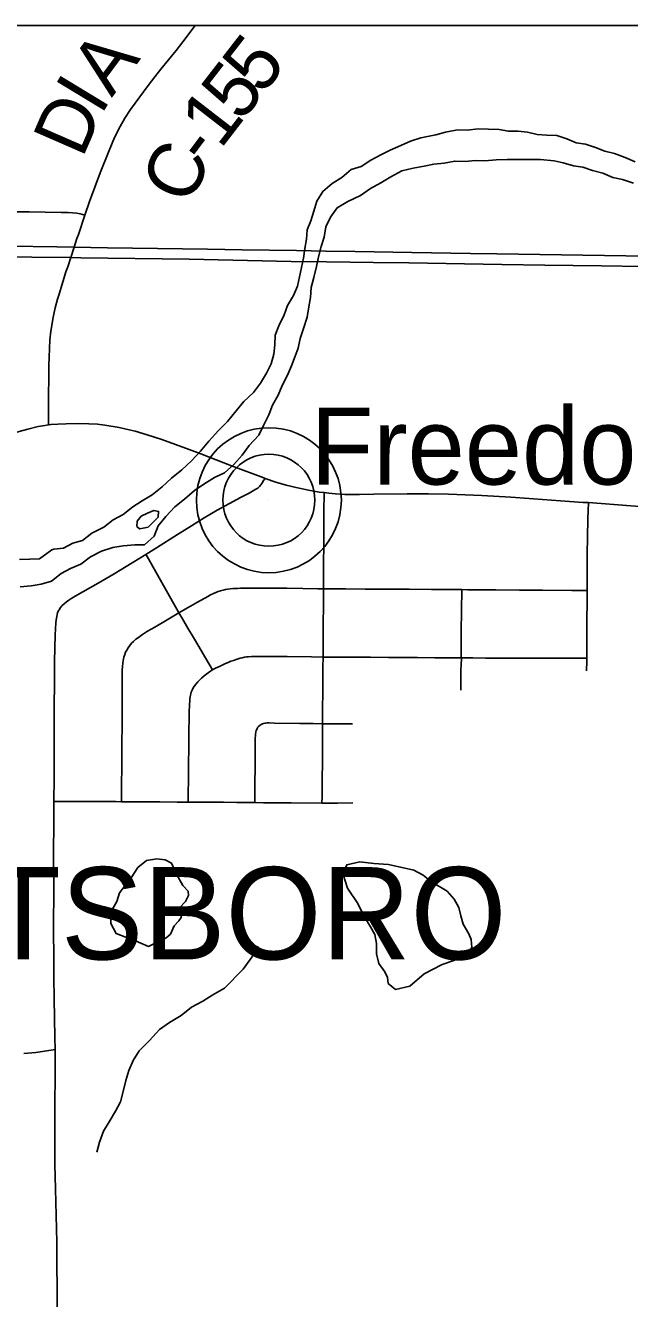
# Model space of a CAD drawing. Extents: x 0 to 34, y 0 to 22.
# Drawn here: x 5.511 to 6.131, y 19.311 to 20.617 of the extents above; entities that cross this region are included whole.
import ezdxf

# ---------------------------------------------------------------- set-up
doc = ezdxf.new("R2010")
doc.units = 0
for name, color, linetype in [('GM_X_Corporation', 7, 'Continuous'), ('GM_X_Corporation_Text', 7, 'Continuous'), ('GM_X_County_Road', 7, 'Continuous'), ('GM_X_County_Road_Text', 7, 'Continuous'), ('GM_X_Interstate_Route', 7, 'Continuous'), ('GM_X_Major_River', 7, 'Continuous'), ('GM_X_Minor_Lake', 7, 'Continuous'), ('GM_X_Minor_River', 7, 'Continuous'), ('GM_X_State_Route', 7, 'Continuous'), ('GM_X_Township_Road', 7, 'Continuous'), ('GM_X_Unincorporated', 7, 'Continuous'), ('GM_X_Unincorporated_Location', 7, 'Continuous'), ('GM_X_Unincorporated_Text', 7, 'Continuous'), ('SH_Data', 7, 'Continuous')]:
    doc.layers.add(name, color=color, linetype=linetype)

msp = doc.modelspace()

# ---------------------------------------------------------------- linework, layer by layer
at = {"layer": 'GM_X_Corporation'}
msp.add_lwpolyline([(8.914, 20.6173), (5.0338, 20.6173)], dxfattribs=at)
at = {"layer": 'GM_X_County_Road'}
for points in [[(5.5718, 20.4227), (5.5766, 20.4368), (5.5873, 20.466), (5.5966, 20.4891), (5.6022, 20.5023), (5.6078, 20.5135), (5.6127, 20.5222), (5.6185, 20.5311), (5.6366, 20.5556), (5.6435, 20.5645), (5.6497, 20.5723), (5.6653, 20.5916), (5.6722, 20.6004), (5.6849, 20.6173)], [(5.5387, 20.3154), (5.5388, 20.3164), (5.5413, 20.3274), (5.5437, 20.3364), (5.5449, 20.3406), (5.5462, 20.3448), (5.5472, 20.3483), (5.5523, 20.3644), (5.5541, 20.3696), (5.5572, 20.379), (5.5607, 20.3897), (5.5636, 20.3986), (5.565, 20.4027), (5.5718, 20.4227)], [(5.5342, 20.2074), (5.5342, 20.2173), (5.5344, 20.2289), (5.5342, 20.2356), (5.5346, 20.258), (5.5347, 20.2682), (5.5349, 20.2768), (5.5358, 20.2948), (5.5366, 20.3035), (5.5387, 20.3154)], [(5.423, 20.1689), (5.4421, 20.1772), (5.4639, 20.1863), (5.4773, 20.1914), (5.4931, 20.1971), (5.5041, 20.2006), (5.513, 20.203), (5.5236, 20.2056), (5.5307, 20.2069), (5.5342, 20.2074)], [(5.5398, 19.8211), (5.5401, 19.845), (5.5401, 19.8611), (5.5401, 19.879), (5.5401, 19.9029), (5.5401, 19.9222), (5.5404, 19.939), (5.5406, 19.9651), (5.5412, 19.9919), (5.5419, 20.0043), (5.5422, 20.0075), (5.5428, 20.0109), (5.5432, 20.0128), (5.5437, 20.0145), (5.5444, 20.0161), (5.5452, 20.0177), (5.5467, 20.0199)], [(5.5411, 19.5664), (5.5409, 19.5788), (5.5401, 19.6188), (5.5397, 19.6406), (5.5397, 19.6661), (5.5395, 19.6835), (5.5395, 19.6966), (5.5399, 19.7264), (5.5394, 19.766), (5.5397, 19.8015), (5.5398, 19.8211)], [(5.5434, 19.2978), (5.5429, 19.3687), (5.5417, 19.4234), (5.541, 19.4483), (5.5407, 19.4731), (5.5407, 19.4924), (5.5409, 19.5146), (5.5411, 19.5351), (5.5411, 19.5664)]]:
    msp.add_lwpolyline(points, dxfattribs=at)
at = {"layer": 'GM_X_Interstate_Route'}
for points in [[(5.0396, 20.398), (5.1655, 20.3959), (5.2516, 20.3944), (5.3154, 20.3934), (5.3505, 20.3929), (5.4941, 20.3908), (5.5428, 20.39), (5.5607, 20.3897), (5.5948, 20.3892), (5.6975, 20.3876), (5.733, 20.3871), (5.7889, 20.3862), (5.8192, 20.3858), (5.8492, 20.3853), (5.9073, 20.3843), (5.9674, 20.3834), (5.9946, 20.383), (6.061, 20.3819), (6.1271, 20.3809), (6.1811, 20.3797)], [(5.0386, 20.387), (5.1051, 20.386), (5.1744, 20.3851), (5.2381, 20.3842), (5.287, 20.3833), (5.3339, 20.3825), (5.3734, 20.3818), (5.4385, 20.3808), (5.4778, 20.3802), (5.5171, 20.3796), (5.5572, 20.379), (5.5674, 20.3789), (5.6788, 20.3774), (5.7835, 20.3752), (5.8199, 20.3748), (5.8681, 20.3742), (5.9044, 20.3738), (5.9999, 20.3721), (6.0438, 20.3714), (6.1022, 20.3705), (6.1443, 20.3698)]]:
    msp.add_lwpolyline(points, dxfattribs=at)
at = {"layer": 'GM_X_Major_River'}
msp.add_line((5.6368, 20.1023), (5.647, 20.1126), dxfattribs=at)
for points in [[(6.0759, 20.4967), (6.0664, 20.5008), (6.0561, 20.5042), (6.0459, 20.5048), (6.0361, 20.5055), (6.0262, 20.5077), (6.0164, 20.5088), (6.0065, 20.5087), (5.9971, 20.5105), (5.9861, 20.5108), (5.9755, 20.5111), (5.9641, 20.5099), (5.9543, 20.5102), (5.9418, 20.5078), (5.932, 20.5051), (5.9165, 20.5019), (5.9059, 20.4985), (5.8961, 20.4942), (5.8852, 20.4892), (5.8754, 20.4846), (5.8652, 20.4792), (5.8554, 20.4727), (5.8452, 20.4695), (5.8354, 20.4611), (5.8256, 20.455), (5.8159, 20.4469), (5.8099, 20.437), (5.8066, 20.4268), (5.8036, 20.4169), (5.7999, 20.4074), (5.7992, 20.3979), (5.7974, 20.3884), (5.796, 20.3785), (5.7941, 20.369), (5.7919, 20.3595), (5.7901, 20.3496), (5.786, 20.3401), (5.7797, 20.3298), (5.7763, 20.3203), (5.7708, 20.3089), (5.767, 20.2994), (5.7667, 20.2895), (5.7657, 20.28), (5.7631, 20.2702), (5.7583, 20.2606), (5.7519, 20.2503), (5.7448, 20.2408), (5.735, 20.2313), (5.7271, 20.2217), (5.7181, 20.211), (5.7088, 20.2015), (5.699, 20.1908), (5.6904, 20.1805), (5.681, 20.1705), (5.6712, 20.1613), (5.6607, 20.1529), (5.6509, 20.1437), (5.6408, 20.1357), (5.6306, 20.1296), (5.6208, 20.1234), (5.611, 20.1154), (5.6008, 20.11), (5.591, 20.1023), (5.579, 20.0962), (5.5692, 20.0889), (5.5594, 20.0861), (5.5496, 20.0808), (5.5397, 20.0799), (5.5379, 20.0792)], [(6.1366, 20.4775), (6.1263, 20.4819), (6.1153, 20.486), (6.1055, 20.4882), (6.096, 20.4919), (6.0857, 20.4953), (6.0759, 20.4967)], [(5.7875, 20.2779), (5.7907, 20.286), (5.7928, 20.2962), (5.7961, 20.3062), (5.7998, 20.318), (5.8016, 20.3286), (5.8033, 20.3381), (5.804, 20.3484), (5.8069, 20.3587), (5.8094, 20.3701), (5.8116, 20.38), (5.8141, 20.3903), (5.8174, 20.4002), (5.8192, 20.4105), (5.824, 20.4204), (5.8307, 20.43), (5.8416, 20.4366), (5.8548, 20.4428), (5.865, 20.4501), (5.8755, 20.4559), (5.8857, 20.4621), (5.897, 20.468), (5.9087, 20.4708), (5.92, 20.4728), (5.9298, 20.4748), (5.9404, 20.4761), (5.9514, 20.4781), (5.962, 20.4778), (5.9722, 20.4787), (5.9824, 20.4785), (5.9938, 20.4794), (6.0052, 20.4799), (6.0173, 20.4796), (6.0396, 20.4799), (6.0533, 20.4785), (6.0628, 20.4764), (6.0734, 20.4731), (6.0829, 20.472), (6.0928, 20.4684), (6.1034, 20.4658), (6.1137, 20.4614), (6.1236, 20.4592), (6.135, 20.4556)], [(5.5053, 20.0411), (5.5167, 20.0423), (5.5269, 20.044), (5.5375, 20.0471), (5.5472, 20.0548), (5.557, 20.0599), (5.5676, 20.0646), (5.5773, 20.0719), (5.5886, 20.0777), (5.6003, 20.0817), (5.6109, 20.0833), (5.623, 20.0842), (5.6329, 20.0843), (5.643, 20.0932), (5.647, 20.1039), (5.6549, 20.1135), (5.6642, 20.1234), (5.674, 20.1311), (5.6841, 20.14), (5.6939, 20.1466), (5.7048, 20.1535), (5.715, 20.1582), (5.7247, 20.1667), (5.733, 20.1763), (5.7404, 20.1862), (5.7502, 20.197), (5.755, 20.2069), (5.7605, 20.2176), (5.7642, 20.2275), (5.7702, 20.2378), (5.7742, 20.2478), (5.7798, 20.2585), (5.7838, 20.268), (5.7875, 20.2779)], [(5.647, 20.1126), (5.6473, 20.1187), (5.6424, 20.1194), (5.636, 20.1167), (5.6296, 20.1136), (5.6254, 20.1087), (5.6251, 20.1033), (5.6278, 20.1007), (5.6316, 20.1015), (5.6368, 20.1023)], [(5.5379, 20.0792), (5.5251, 20.07), (5.5152, 20.0695), (5.5046, 20.0694)]]:
    msp.add_lwpolyline(points, dxfattribs=at)
at = {"layer": 'GM_X_Minor_Lake'}
for p, q in [((5.6192, 19.7426), (5.6072, 19.7273)), ((5.9436, 19.7291), (5.9277, 19.7385))]:
    msp.add_line(p, q, dxfattribs=at)
for points in [[(5.6072, 19.7273), (5.6046, 19.7182), (5.5979, 19.7071), (5.5983, 19.6958), (5.6037, 19.6856), (5.6128, 19.6822), (5.6235, 19.6781), (5.6371, 19.6722), (5.6552, 19.681), (5.6597, 19.6849), (5.6635, 19.6932), (5.6683, 19.6986), (5.6706, 19.702), (5.6709, 19.7062), (5.669, 19.7119), (5.675, 19.7183), (5.678, 19.7244), (5.6776, 19.729), (5.6722, 19.7346), (5.6657, 19.7463), (5.6607, 19.7577), (5.6542, 19.7611), (5.6455, 19.7621), (5.6349, 19.7605), (5.6259, 19.7532), (5.6192, 19.7426)], [(5.9277, 19.7385), (5.9189, 19.7452), (5.9094, 19.7505), (5.8833, 19.7564), (5.8685, 19.7574), (5.8541, 19.7592), (5.8405, 19.756), (5.8364, 19.7469), (5.8414, 19.7321), (5.8518, 19.7163), (5.8579, 19.7038), (5.8648, 19.6925), (5.8694, 19.6846), (5.871, 19.6751), (5.8711, 19.6645), (5.8734, 19.6546), (5.8796, 19.6463), (5.8823, 19.6403), (5.8831, 19.6342), (5.8907, 19.6282), (5.9054, 19.6314), (5.9201, 19.644), (5.9385, 19.6536), (5.9506, 19.6579), (5.9638, 19.6637), (5.9691, 19.6713), (5.9683, 19.6792), (5.9659, 19.6853), (5.9602, 19.6951), (5.9578, 19.7038), (5.9555, 19.7122), (5.9509, 19.7208), (5.9436, 19.7291)]]:
    msp.add_lwpolyline(points, dxfattribs=at)
at = {"layer": 'GM_X_Minor_River'}
msp.add_lwpolyline([(5.5839, 19.4612), (5.5868, 19.4715), (5.5909, 19.4825), (5.5965, 19.4921), (5.6032, 19.5031), (5.6081, 19.5126), (5.6114, 19.5248), (5.6136, 19.5347), (5.6169, 19.5449), (5.6214, 19.5552), (5.6274, 19.5651), (5.6382, 19.5758), (5.6484, 19.5869), (5.6585, 19.5942), (5.6706, 19.6015), (5.6811, 19.6099), (5.6928, 19.6161), (5.703, 19.6226), (5.715, 19.6295), (5.7342, 19.649), (5.7413, 19.6589), (5.7481, 19.6685), (5.7492, 19.6726)], dxfattribs=at)
at = {"layer": 'GM_X_State_Route'}
for points in [[(5.423, 20.1689), (5.4421, 20.1772), (5.4639, 20.1863), (5.4773, 20.1914), (5.4931, 20.1971), (5.5041, 20.2006), (5.513, 20.203), (5.5236, 20.2056), (5.5307, 20.2069), (5.5342, 20.2074)], [(5.5342, 20.2074), (5.5367, 20.2078), (5.5441, 20.2083), (5.5524, 20.2086), (5.5653, 20.2087), (5.5756, 20.2086), (5.5848, 20.2081), (5.5921, 20.2072), (5.6068, 20.2046), (5.6172, 20.2023), (5.6232, 20.2008), (5.6358, 20.1972), (5.6506, 20.1923), (5.6787, 20.1823), (5.6909, 20.1776), (5.7222, 20.1655), (5.7553, 20.153), (5.7567, 20.1525), (5.7676, 20.1488), (5.7783, 20.1456), (5.7885, 20.143), (5.8013, 20.1404), (5.8123, 20.1385), (5.8172, 20.1379), (5.8221, 20.1373), (5.8289, 20.1366), (5.8387, 20.1361), (5.8536, 20.136), (5.8685, 20.1363), (5.9027, 20.1367), (5.9083, 20.1366), (5.9245, 20.1366), (5.945, 20.1363), (5.9537, 20.136), (5.9792, 20.1349), (6.009, 20.1331)], [(6.009, 20.1331), (6.0139, 20.1328), (6.0598, 20.1295), (6.0834, 20.1279), (6.0887, 20.1276)], [(6.0887, 20.1276), (6.1323, 20.1244), (6.1554, 20.1228), (6.1781, 20.1212), (6.2199, 20.1179), (6.228, 20.1172)]]:
    msp.add_lwpolyline(points, dxfattribs=at)
at = {"layer": 'GM_X_Township_Road'}
for points in [[(5.2828, 20.4292), (5.2999, 20.4289), (5.3273, 20.4285), (5.3535, 20.428), (5.3826, 20.4276), (5.4094, 20.4272), (5.4481, 20.4266), (5.4846, 20.4262), (5.5144, 20.4259), (5.5472, 20.4255), (5.5547, 20.4254), (5.5591, 20.4251), (5.5634, 20.4245), (5.5669, 20.4239), (5.5718, 20.4227)], [(5.6342, 20.0745), (5.6453, 20.0812), (5.6669, 20.0948), (5.681, 20.1038), (5.6942, 20.1119), (5.7076, 20.1198), (5.7202, 20.1267), (5.7322, 20.1332), (5.7405, 20.1375), (5.7471, 20.1413), (5.7492, 20.1426), (5.7511, 20.1443), (5.7525, 20.146), (5.7534, 20.1472), (5.7552, 20.1502), (5.7567, 20.1525)], [(5.8166, 20.0393), (5.8166, 20.0442), (5.8168, 20.0634), (5.8169, 20.0861), (5.8171, 20.1056), (5.8171, 20.1205), (5.8172, 20.1357), (5.8172, 20.1379)], [(6.0872, 20.0374), (6.0873, 20.0599), (6.0875, 20.0712), (6.0878, 20.0958), (6.088, 20.1074), (6.0881, 20.1133), (6.0882, 20.1173), (6.0884, 20.1215), (6.0886, 20.1251), (6.0887, 20.1276)], [(5.5467, 20.0199), (5.5484, 20.022), (5.5504, 20.0238), (5.5529, 20.0258), (5.5552, 20.0276), (5.5582, 20.0296), (5.5616, 20.0317), (5.5852, 20.0449), (5.6018, 20.0546), (5.614, 20.062), (5.6342, 20.0745)], [(5.6682, 20.0145), (5.666, 20.0183), (5.6355, 20.0722), (5.6342, 20.0745)], [(5.6682, 20.0145), (5.6722, 20.0168), (5.6801, 20.0213), (5.6872, 20.0255), (5.6978, 20.0314), (5.7008, 20.0329), (5.7039, 20.0344), (5.7062, 20.0353), (5.7087, 20.0363), (5.711, 20.0372), (5.7136, 20.0379), (5.7161, 20.0385), (5.7185, 20.0389), (5.7208, 20.0392), (5.7237, 20.0395), (5.726, 20.0396), (5.7283, 20.0396), (5.7316, 20.0398), (5.7361, 20.0398), (5.7444, 20.0398), (5.7551, 20.0398), (5.7655, 20.0397), (5.779, 20.0397), (5.7954, 20.0395), (5.8107, 20.0393), (5.8166, 20.0393)], [(5.8162, 19.9692), (5.8163, 19.9766), (5.8164, 19.9999), (5.8165, 20.025), (5.8166, 20.0393)], [(5.8166, 20.0393), (5.8235, 20.0392), (5.8392, 20.0392), (5.8595, 20.039), (5.8796, 20.0389), (5.9047, 20.0388), (5.9275, 20.0386), (5.9407, 20.0385), (5.9546, 20.0384), (5.9588, 20.0384)], [(5.9579, 19.9683), (5.958, 19.9781), (5.9581, 19.9883), (5.9581, 19.9999), (5.9582, 20.0121), (5.9583, 20.0183), (5.9584, 20.0226), (5.9586, 20.0324), (5.9588, 20.0372), (5.9588, 20.0384)], [(5.9588, 20.0384), (5.9649, 20.0383), (5.979, 20.0383), (5.9936, 20.0382), (6.0178, 20.0379), (6.0416, 20.0378), (6.0717, 20.0375), (6.0861, 20.0374), (6.0872, 20.0374)], [(6.087, 19.9679), (6.087, 19.9763), (6.0871, 19.9874), (6.0871, 20.0033), (6.0872, 20.0296), (6.0872, 20.0374)], [(5.6092, 19.8207), (5.6093, 19.8232), (5.6094, 19.839), (5.6095, 19.8555), (5.6097, 19.876), (5.6099, 19.9034), (5.61, 19.9193), (5.61, 19.9384), (5.6101, 19.9498), (5.6101, 19.9558), (5.6102, 19.9594), (5.6105, 19.9629), (5.6109, 19.9658), (5.6118, 19.969), (5.6126, 19.9717), (5.6135, 19.9741), (5.6146, 19.9762), (5.6161, 19.9786), (5.6179, 19.9811), (5.6197, 19.9833), (5.6216, 19.9852), (5.6241, 19.9874), (5.6268, 19.9894), (5.6308, 19.9924), (5.6361, 19.9956), (5.6434, 20), (5.6563, 20.0075), (5.6682, 20.0145)], [(5.7026, 19.9561), (5.6994, 19.9619), (5.6925, 19.9736), (5.6887, 19.98), (5.6831, 19.9893), (5.6774, 19.9989), (5.6718, 20.0085), (5.6682, 20.0145)], [(5.7026, 19.9561), (5.7057, 19.9576), (5.7105, 19.9599), (5.7161, 19.9624), (5.7187, 19.9635), (5.7217, 19.9648), (5.7244, 19.9658), (5.7279, 19.967), (5.7311, 19.968), (5.7331, 19.9685), (5.7355, 19.9689), (5.7376, 19.9693), (5.7396, 19.9695), (5.7429, 19.9697), (5.7456, 19.9699), (5.7486, 19.9699), (5.7543, 19.9698), (5.7642, 19.9697), (5.7794, 19.9696), (5.8045, 19.9693), (5.8162, 19.9692)], [(5.8157, 19.9008), (5.8157, 19.9076), (5.8159, 19.9416), (5.8161, 19.9588), (5.8162, 19.9692)], [(5.8162, 19.9692), (5.8243, 19.9692), (5.8468, 19.969), (5.8649, 19.9689), (5.8835, 19.9687), (5.8973, 19.9687), (5.913, 19.9686), (5.931, 19.9685), (5.9531, 19.9683), (5.9579, 19.9683)], [(5.9575, 19.9352), (5.9576, 19.9424), (5.9578, 19.9552), (5.9579, 19.9619), (5.9583, 19.9669), (5.9579, 19.9683)], [(5.9579, 19.9683), (5.963, 19.9683), (5.97, 19.9683), (5.9829, 19.9682), (5.9979, 19.9682), (6.018, 19.9682), (6.0342, 19.9681), (6.058, 19.968), (6.0752, 19.968), (6.0858, 19.9679), (6.087, 19.9679)], [(6.0868, 19.955), (6.0869, 19.965), (6.087, 19.9679)], [(5.6776, 19.8204), (5.6777, 19.8296), (5.678, 19.8432), (5.6781, 19.8545), (5.6784, 19.8811), (5.6785, 19.8934), (5.6787, 19.9063), (5.6789, 19.9146), (5.679, 19.9181), (5.6792, 19.9211), (5.6793, 19.9235), (5.6795, 19.9259), (5.6798, 19.9283), (5.6801, 19.9301), (5.6804, 19.9314), (5.6809, 19.9333), (5.6817, 19.9353), (5.6829, 19.9375), (5.6845, 19.9399), (5.6858, 19.9417), (5.6875, 19.9437), (5.6894, 19.9456), (5.6914, 19.9476), (5.694, 19.9498), (5.6968, 19.9519), (5.6997, 19.954), (5.7026, 19.9561)], [(5.7463, 19.8198), (5.7463, 19.8361), (5.7465, 19.8596), (5.7466, 19.881), (5.7466, 19.8838), (5.7466, 19.8863), (5.7467, 19.8885), (5.7469, 19.8903), (5.7471, 19.8916), (5.7473, 19.8926), (5.7476, 19.8938), (5.7481, 19.895), (5.7486, 19.896), (5.7494, 19.8972), (5.7503, 19.8983), (5.7517, 19.8994), (5.7528, 19.9001), (5.7539, 19.9007), (5.755, 19.901), (5.7563, 19.9013), (5.7576, 19.9015), (5.7589, 19.9016), (5.7608, 19.9016), (5.7663, 19.9015), (5.7922, 19.9011), (5.8059, 19.901), (5.8157, 19.9008)], [(5.8151, 19.8193), (5.8152, 19.8265), (5.8153, 19.8345), (5.8154, 19.8452), (5.8155, 19.8598), (5.8156, 19.8772), (5.8157, 19.8908), (5.8157, 19.9008)], [(5.8157, 19.9008), (5.8218, 19.9008), (5.8314, 19.9008), (5.8428, 19.9008), (5.8463, 19.9008)], [(5.5398, 19.8211), (5.5497, 19.8211), (5.5645, 19.8211), (5.5787, 19.8211), (5.5861, 19.8208), (5.6034, 19.8208), (5.6092, 19.8207)], [(5.6092, 19.8207), (5.6169, 19.8207), (5.6411, 19.8205), (5.6485, 19.8205), (5.6665, 19.8203), (5.6727, 19.8203), (5.6776, 19.8204)], [(5.6776, 19.8204), (5.6795, 19.8204), (5.6962, 19.8204), (5.7061, 19.8203), (5.7141, 19.8202), (5.7278, 19.82), (5.7463, 19.8198)], [(5.7463, 19.8198), (5.7551, 19.8197), (5.7712, 19.8197), (5.781, 19.8196), (5.7834, 19.8196), (5.8151, 19.8193)], [(5.8151, 19.8193), (5.8206, 19.8192), (5.8312, 19.8192), (5.8468, 19.8197)], [(5.5091, 19.5622), (5.5215, 19.5635), (5.5325, 19.5651), (5.5411, 19.5664)]]:
    msp.add_lwpolyline(points, dxfattribs=at)
at = {"layer": 'GM_X_Unincorporated'}
for radius in [0.0744, 0.0472]:
    msp.add_circle((5.7606, 20.1301), radius, dxfattribs=at)
at = {"layer": 'GM_X_Unincorporated_Location'}
msp.add_line((5.7606, 20.1301), (5.7606, 20.1301), dxfattribs=at)
at = {"layer": 'SH_Data'}
msp.add_line((2.114, 20.6173), (8.914, 20.6173), dxfattribs=at)

# ---------------------------------------------------------------- texts
at = {"layer": 'GM_X_Corporation_Text'}
msp.add_text('STREETSBORO', height=0.094697, rotation=0, dxfattribs=at).set_placement((5.0476, 19.6589))
at = {"layer": 'GM_X_County_Road_Text'}
for s, rotation, p in [('5', 52.1497, (5.7537, 20.5448)), ('A', 53.3261, (5.5993, 20.5428)), ('5', 52.1944, (5.7322, 20.5171)), ('I', 58.7832, (5.588, 20.524)), ('D', 66.4551, (5.569, 20.48)), ('1', 52.2797, (5.7108, 20.4894)), ('-', 53.0911, (5.6969, 20.471)), ('C', 66.0942, (5.6797, 20.4312))]:
    msp.add_text(s, height=0.0568, rotation=rotation, dxfattribs=at).set_placement(p)
at = {"layer": 'GM_X_Unincorporated_Text'}
msp.add_text('Freedom Dam', height=0.078977, rotation=0, dxfattribs=at).set_placement((5.8033, 20.1462))

doc.saveas('drawing.dxf')
